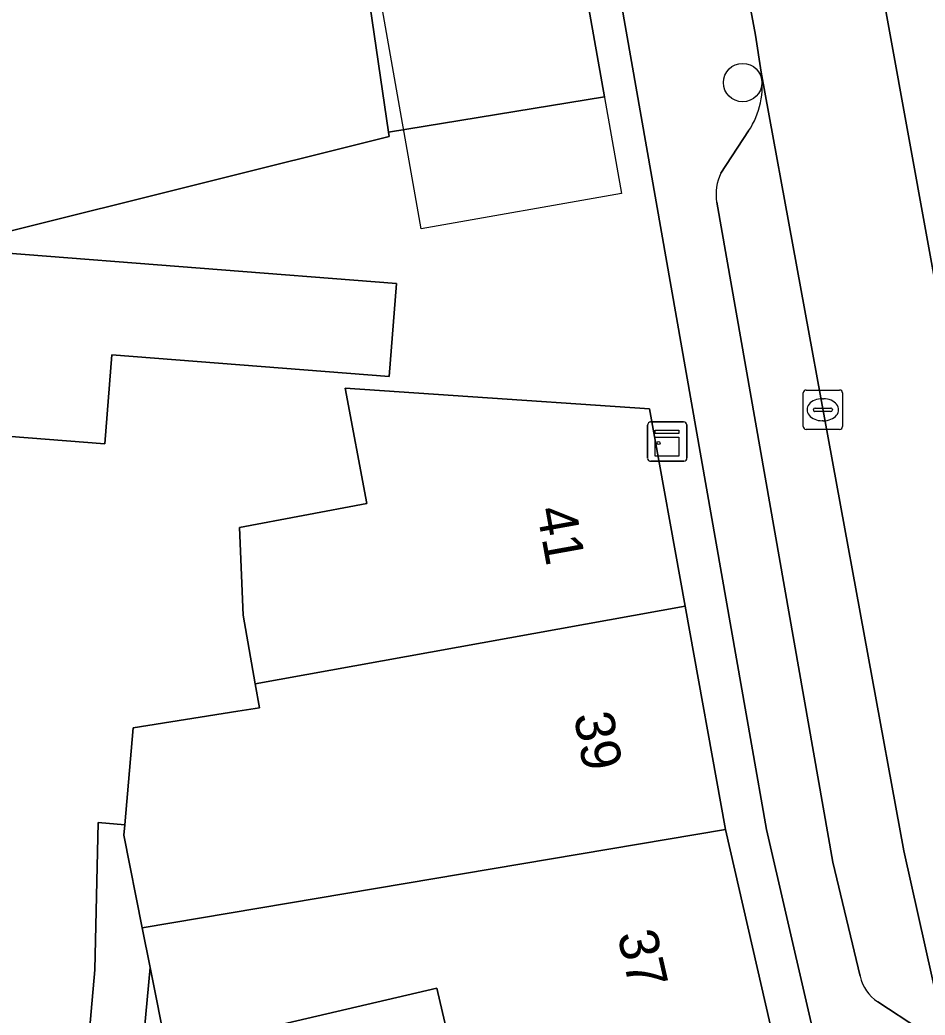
# Model space of a CAD drawing. Extents: x 160856 to 161310, y 384024 to 384878.
# Drawn here: x 160956.66 to 160979.67, y 384818.67 to 384843.96 of the extents above; entities that cross this region are included whole.
import ezdxf

# ---------------------------------------------------------------- set-up
doc = ezdxf.new("R2010")
doc.units = 0
for name, color, linetype in [('IMGEO_Boom', 7, 'Continuous'), ('IMGEO_Erf', 7, 'Continuous'), ('IMGEO_Kast', 7, 'Continuous'), ('IMGEO_Kolk', 7, 'Continuous'), ('IMGEO_Pand', 7, 'Continuous'), ('IMGEO_Pand_nummerreeks', 7, 'Continuous'), ('IMGEO_Pand_vergunning_verleend', 7, 'Continuous'), ('IMGEO_Parkeervlak_open', 7, 'Continuous'), ('IMGEO_Rijbaan_lokaal_open', 7, 'Continuous'), ('IMGEO_Voetpad_open', 7, 'Continuous')]:
    doc.layers.add(name, color=color, linetype=linetype)

msp = doc.modelspace()

# ---------------------------------------------------------------- linework, layer by layer
at = {"layer": 'IMGEO_Boom'}
msp.add_circle((160975.037, 384842.367), 0.489, dxfattribs=at)
at = {"layer": 'IMGEO_Erf'}
for points in [[(160980.654, 384801.69), (160975.639, 384823.391), (160970.553, 384852.358), (160970.051, 384855.218), (160969.221, 384855), (160971.52, 384842.007), (160966.03, 384841.11), (160966.048, 384840.993), (160961.197, 384839.783), (160936.502, 384833.624)], [(160956.275, 384793.744), (160958.566, 384819.819), (160958.656, 384823.569), (160959.326, 384823.509), (160959.546, 384825.972), (160962.205, 384826.393), (160962.755, 384826.48), (160962.647, 384827.086), (160962.335, 384828.832), (160962.245, 384831.065), (160965.479, 384831.671), (160964.93, 384834.605), (160967.676, 384834.418), (160972.664, 384834.076), (160973.571, 384829.064), (160974.598, 384823.39), (160975.854, 384817.922)]]:
    msp.add_lwpolyline(points, dxfattribs=at)
for points in [[(160958.824, 384833.185), (160954.371, 384833.532), (160954.55, 384835.82), (160956.072, 384835.701), (160956.254, 384838.041), (160966.234, 384837.263), (160966.05, 384834.898), (160959.001, 384835.447)], [(160958.824, 384833.185), (160959.001, 384835.447), (160966.05, 384834.898), (160966.234, 384837.263), (160956.254, 384838.041), (160956.072, 384835.701), (160954.55, 384835.82), (160954.371, 384833.532)], [(160965.446, 384809.795), (160964.693, 384813.026), (160968.53, 384813.92), (160968.016, 384816.123), (160967.262, 384819.358), (160960.397, 384817.757), (160959.974, 384819.878), (160959.274, 384812.307), (160961.568, 384812.871), (160962.213, 384809.053), (160962.621, 384806.628), (160958.756, 384805.976), (160958.33, 384800.056), (160961.112, 384800.658), (160961.825, 384797.445), (160968.14, 384798.8), (160967.511, 384801.53), (160971.212, 384802.392), (160970.551, 384805.228), (160969.863, 384808.183), (160966.03, 384807.289)]]:
    msp.add_lwpolyline(points, close=True, dxfattribs=at)
at = {"layer": 'IMGEO_Kast'}
for p, q in [((160972.619, 384832.819), (160972.619, 384833.66)), ((160972.619, 384833.66), (160972.619, 384832.819)), ((160972.694, 384833.744), (160973.535, 384833.744)), ((160973.535, 384833.744), (160972.694, 384833.744)), ((160973.619, 384833.669), (160973.619, 384832.828)), ((160973.619, 384832.828), (160973.619, 384833.669)), ((160973.544, 384832.744), (160972.703, 384832.744)), ((160972.703, 384832.744), (160973.544, 384832.744))]:
    msp.add_line(p, q, dxfattribs=at)
for points in [[(160972.814, 384833.534), (160973.414, 384833.534), (160973.414, 384833.449), (160972.814, 384833.449), (160972.814, 384833.534)], [(160972.814, 384833.359), (160973.414, 384833.359), (160973.414, 384832.87), (160972.814, 384832.87), (160972.814, 384833.359)]]:
    msp.add_lwpolyline(points, dxfattribs=at)
msp.add_circle((160972.898, 384833.208), 0.0377, dxfattribs=at)
for centre, start, end in [((160972.697, 384833.666), 92.4484, 184.2845), ((160972.697, 384833.666), 92.4484, 184.2845), ((160973.541, 384833.666), 2.4484, 94.2845), ((160973.541, 384833.666), 2.4484, 94.2845), ((160972.697, 384832.822), 182.4484, 274.2845), ((160972.697, 384832.822), 182.4484, 274.2845), ((160973.541, 384832.822), 272.4484, 4.2845), ((160973.541, 384832.822), 272.4484, 4.2845)]:
    msp.add_arc(centre, 0.0779, start, end, dxfattribs=at)
at = {"layer": 'IMGEO_Kolk'}
for p, q in [((160976.649, 384834.553), (160977.501, 384834.553)), ((160976.574, 384833.627), (160976.574, 384834.479)), ((160977.062, 384834.333), (160977.087, 384834.333)), ((160977.575, 384834.479), (160977.575, 384833.627)), ((160976.833, 384834.047), (160976.833, 384834.059)), ((160976.876, 384834.096), (160977.274, 384834.096)), ((160977.317, 384834.059), (160977.317, 384834.047)), ((160977.271, 384834.01), (160976.873, 384834.01)), ((160977.501, 384833.553), (160976.649, 384833.553)), ((160977.085, 384833.773), (160977.06, 384833.773))]:
    msp.add_line(p, q, dxfattribs=at)
for points in [[(160976.649, 384834.553), (160977.501, 384834.553)], [(160976.574, 384833.627), (160976.574, 384834.479)], [(160977.575, 384834.479), (160977.575, 384833.627)], [(160977.501, 384833.553), (160976.649, 384833.553)]]:
    msp.add_lwpolyline(points, dxfattribs=at)
for centre, radius, start, end in [((160976.651, 384834.477), 0.0765, 91.552, 178.448), ((160976.651, 384834.477), 0.0765, 91.552, 178.448), ((160977.499, 384834.477), 0.0765, 1.552, 88.448), ((160977.499, 384834.477), 0.0765, 1.552, 88.448), ((160976.873, 384834.056), 0.0403, 85.8775, 175.7526), ((160976.87, 384834.046), 0.0366, 178.938, 274.7102), ((160977.274, 384834.053), 0.043, 264.8664, 352.4533), ((160977.278, 384834.058), 0.0386, 1.7309, 96.639), ((160976.651, 384833.629), 0.0765, 181.552, 268.448), ((160976.651, 384833.629), 0.0765, 181.552, 268.448), ((160977.499, 384833.629), 0.0765, 271.552, 358.448), ((160977.499, 384833.629), 0.0765, 271.552, 358.448)]:
    msp.add_arc(centre, radius, start, end, dxfattribs=at)
for centre, major_axis, ratio, start_param, end_param in [((160977.061, 384834.053), (-0.387, 0.002), 0.722429, 4.712389, 7.853982), ((160977.086, 384834.053), (-0.39, 0.002), 0.717154, 1.570796, 4.712389)]:
    msp.add_ellipse(centre, major_axis=major_axis, ratio=ratio, start_param=start_param, end_param=end_param, dxfattribs=at)
at = {"layer": 'IMGEO_Pand'}
for points in [[(160969.221, 384855), (160964.114, 384854.203), (160966.03, 384841.11), (160971.52, 384842.007)], [(160964.114, 384854.203), (160940.701, 384848.385), (160941.007, 384847.17), (160936.87, 384846.14), (160936.557, 384847.335), (160934.872, 384846.924), (160935.042, 384846.159), (160933.864, 384844.174), (160935.077, 384839.324), (160936.502, 384833.624), (160961.197, 384839.783), (160966.048, 384840.993), (160966.03, 384841.11)], [(160973.571, 384829.064), (160972.664, 384834.076), (160967.676, 384834.418), (160964.93, 384834.605), (160965.479, 384831.671), (160962.245, 384831.065), (160962.335, 384828.832), (160962.647, 384827.086)], [(160973.571, 384829.064), (160962.647, 384827.086), (160962.755, 384826.48), (160962.205, 384826.393), (160959.546, 384825.972), (160959.326, 384823.509), (160959.303, 384823.247), (160959.773, 384820.887), (160974.598, 384823.39)], [(160974.598, 384823.39), (160959.773, 384820.887), (160959.974, 384819.878), (160960.397, 384817.757), (160967.262, 384819.358), (160968.016, 384816.123), (160968.433, 384816.219), (160975.854, 384817.922)]]:
    msp.add_lwpolyline(points, close=True, dxfattribs=at)
at = {"layer": 'IMGEO_Pand_vergunning_verleend'}
msp.add_lwpolyline([(160964.114, 384854.203), (160969.203, 384855.103), (160971.955, 384839.55), (160966.866, 384838.65)], close=True, dxfattribs=at)
at = {"layer": 'IMGEO_Parkeervlak_open'}
for points in [[(160976.949, 384853.403), (160977.479, 384850.76), (160978.754, 384843.764), (160982.15, 384825.052), (160983.723, 384817.77)], [(160980.396, 384817.197), (160979.13, 384822.843), (160975.504, 384842.631)], [(160975.188, 384841.137), (160974.485, 384840.067)], [(160974.375, 384839.328), (160977.327, 384822.558), (160978.026, 384819.662)], [(160978.474, 384819.007), (160979.533, 384818.317)]]:
    msp.add_lwpolyline(points, dxfattribs=at)
for centre, radius, start, end in [((160973.452, 384842.285), 2.081, 326.532, 9.5825), ((160975.578, 384839.527), 1.22, 153.6978, 189.3695), ((160979.005, 384819.851), 0.997, 190.9128, 237.8291)]:
    msp.add_arc(centre, radius, start, end, dxfattribs=at)
at = {"layer": 'IMGEO_Rijbaan_lokaal_open'}
msp.add_lwpolyline([(160978.754, 384843.764), (160977.479, 384850.76), (160976.949, 384853.403), (160976.934, 384853.479), (160973.549, 384852.917), (160973.754, 384851.919), (160974.84, 384846.396), (160975.364, 384843.569), (160975.504, 384842.631), (160979.13, 384822.843), (160980.396, 384817.197), (160980.425, 384817.077), (160980.859, 384815.191), (160984.148, 384815.959), (160983.735, 384817.713), (160983.723, 384817.77), (160982.15, 384825.052)], close=True, dxfattribs=at)
at = {"layer": 'IMGEO_Voetpad_open'}
for points in [[(160975.504, 384842.631), (160975.364, 384843.569), (160974.84, 384846.396), (160973.754, 384851.919), (160973.549, 384852.917), (160970.553, 384852.358), (160975.639, 384823.391), (160980.654, 384801.69), (160980.906, 384800.6), (160992.6, 384750), (160996.597, 384732.705), (160996.604, 384732.664), (160996.834, 384731.34), (160997.799, 384725.788), (160998.487, 384714.721), (161001.824, 384714.974)], [(160974.485, 384840.067), (160975.188, 384841.137)], [(160978.026, 384819.662), (160977.327, 384822.558), (160974.375, 384839.328)], [(160959.274, 384812.307), (160959.974, 384819.878), (160959.773, 384820.887), (160959.303, 384823.247), (160959.326, 384823.509), (160958.656, 384823.569), (160958.566, 384819.819), (160956.275, 384793.744)], [(160979.533, 384818.317), (160978.474, 384819.007)]]:
    msp.add_lwpolyline(points, dxfattribs=at)
for centre, radius, start, end in [((160973.452, 384842.285), 2.081, 326.532, 9.5825), ((160975.578, 384839.527), 1.22, 153.6978, 189.3695), ((160979.005, 384819.851), 0.997, 190.9128, 237.8291)]:
    msp.add_arc(centre, radius, start, end, dxfattribs=at)

# ---------------------------------------------------------------- texts
at = {"layer": 'IMGEO_Pand_nummerreeks'}
for s, rotation, p in [('41', 280.2615, (160969.793, 384831.522)), ('41', 280.2586, (160969.793, 384831.522)), ('39', 280.2615, (160970.74, 384826.291)), ('37', 282.9372, (160971.845, 384820.719))]:
    msp.add_text(s, height=1, rotation=rotation, dxfattribs=at).set_placement(p)

doc.saveas('drawing.dxf')
